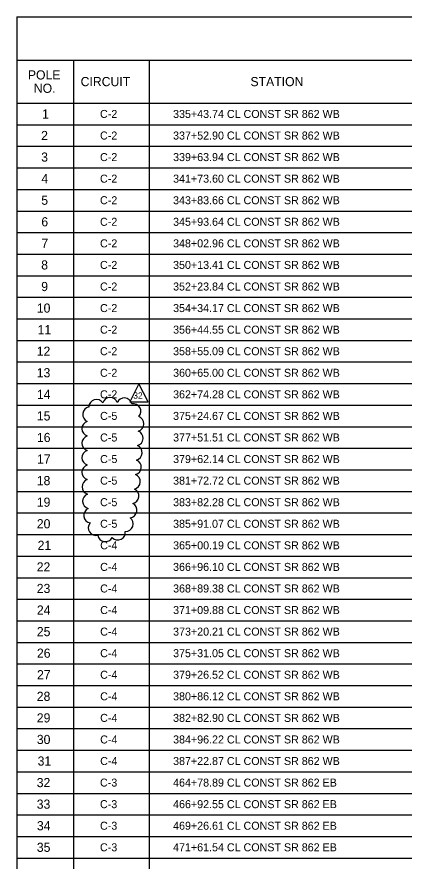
# Model space of a CAD drawing. Extents: x -818.1 to -802.4, y -2198.1 to -2187.9.
# Drawn here: x -817.24 to -814.27, y -2194.32 to -2187.86 of the extents above; entities that cross this region are included whole.
import ezdxf

# ---------------------------------------------------------------- set-up
doc = ezdxf.new("R2010")
doc.units = 0
for name, color, linetype in [('Cloud_dp', 7, 'Continuous'), ('SumBoxBorder_dp', 7, 'Continuous'), ('SumBoxLines_dp', 7, 'Continuous'), ('SumBoxLinesMin_dp', 7, 'Continuous'), ('TextLabel', 7, 'Continuous'), ('TextNotes', 7, 'Continuous')]:
    doc.layers.add(name, color=color, linetype=linetype)

msp = doc.modelspace()

# ---------------------------------------------------------------- linework, layer by layer
at = {"layer": 'Cloud_dp'}
for centre, radius, start, end in [((-816.6297, -2190.8434), 0.0582, 34.08748, 179.08748), ((-816.5257, -2190.8275), 0.0583, 18.3005, 163.3005), ((-816.4165, -2190.8314), 0.0583, 12.67782, 157.67782), ((-816.3478, -2190.8755), 0.0582, 316.71295, 101.71295), ((-816.6769, -2190.8997), 0.0583, 100.80604, 245.80604), ((-816.6833, -2191.0084), 0.0582, 107.5, 252.5), ((-816.3247, -2190.9704), 0.0582, 285.6373, 70.6373), ((-816.6833, -2191.1195), 0.0582, 107.5, 252.5), ((-816.3302, -2191.0807), 0.0582, 283.69742, 68.69742), ((-816.3376, -2191.1916), 0.0582, 283.69742, 68.69742), ((-816.6833, -2191.2306), 0.0582, 107.5, 252.5), ((-816.3449, -2191.3024), 0.0582, 283.69742, 68.69742), ((-816.6832, -2191.3417), 0.0582, 107.56018, 252.56018), ((-816.6822, -2191.4525), 0.0582, 108.55836, 253.55836), ((-816.3526, -2191.4132), 0.0582, 283.38206, 68.38206), ((-816.3626, -2191.5231), 0.0582, 281.1857, 66.1857), ((-816.6782, -2191.5629), 0.0582, 110.52167, 255.52167), ((-816.3785, -2191.6317), 0.0582, 277.15315, 62.15315), ((-816.6686, -2191.6722), 0.0582, 114.59135, 259.59135), ((-816.4065, -2191.7359), 0.0582, 267.75604, 52.75604), ((-816.6343, -2191.7667), 0.0582, 140.26847, 285.26847), ((-816.5613, -2191.8148), 0.0582, 187.97836, 332.97836), ((-816.4665, -2191.8018), 0.0582, 222.63242, 7.63242)]:
    msp.add_arc(centre, radius, start, end, dxfattribs=at)
at = {"layer": 'SumBoxBorder_dp'}
for p, q in [((-817.2394, -2187.8581), (-810.1144, -2187.8581)), ((-817.2394, -2187.8581), (-817.2394, -2195.9431)), ((-817.2394, -2188.1881), (-810.1144, -2188.1881)), ((-817.2394, -2188.1881), (-810.1144, -2188.1881))]:
    msp.add_line(p, q, dxfattribs=at)
at = {"layer": 'SumBoxLines_dp'}
for p, q in [((-816.8044, -2188.1881), (-816.8044, -2195.9431)), ((-816.8044, -2188.1881), (-816.8044, -2195.9431)), ((-816.2269, -2188.1881), (-816.2269, -2194.2931)), ((-816.2269, -2188.1881), (-816.2269, -2195.9431)), ((-817.2394, -2188.5181), (-810.1144, -2188.5181))]:
    msp.add_line(p, q, dxfattribs=at)
at = {"layer": 'SumBoxLinesMin_dp'}
for p, q in [((-817.2394, -2188.5181), (-810.1144, -2188.5181)), ((-817.2394, -2188.6831), (-810.1144, -2188.6831)), ((-817.2394, -2188.6831), (-810.1144, -2188.6831)), ((-817.2394, -2188.8481), (-810.1144, -2188.8481)), ((-817.2394, -2188.8481), (-810.1144, -2188.8481)), ((-817.2394, -2189.0131), (-810.1144, -2189.0131)), ((-817.2394, -2189.0131), (-810.1144, -2189.0131)), ((-817.2394, -2189.1781), (-810.1144, -2189.1781)), ((-817.2394, -2189.1781), (-810.1144, -2189.1781)), ((-817.2394, -2189.3431), (-810.1144, -2189.3431)), ((-817.2394, -2189.3431), (-810.1144, -2189.3431)), ((-817.2394, -2189.5081), (-810.1144, -2189.5081)), ((-817.2394, -2189.5081), (-810.1144, -2189.5081)), ((-817.2394, -2189.6731), (-810.1144, -2189.6731)), ((-817.2394, -2189.6731), (-810.1144, -2189.6731)), ((-817.2394, -2189.8381), (-810.1144, -2189.8381)), ((-817.2394, -2189.8381), (-810.1144, -2189.8381)), ((-817.2394, -2190.0031), (-810.1144, -2190.0031)), ((-817.2394, -2190.0031), (-810.1144, -2190.0031)), ((-817.2394, -2190.1681), (-810.1144, -2190.1681)), ((-817.2394, -2190.1681), (-810.1144, -2190.1681)), ((-817.2394, -2190.3331), (-810.1144, -2190.3331)), ((-817.2394, -2190.3331), (-810.1144, -2190.3331)), ((-817.2394, -2190.4981), (-810.1144, -2190.4981)), ((-817.2394, -2190.4981), (-810.1144, -2190.4981)), ((-817.2394, -2190.6631), (-810.1144, -2190.6631)), ((-817.2394, -2190.6631), (-810.1144, -2190.6631)), ((-817.2394, -2190.8281), (-810.1144, -2190.8281)), ((-817.2394, -2190.8281), (-810.1144, -2190.8281)), ((-817.2394, -2190.9931), (-810.1144, -2190.9931)), ((-817.2394, -2190.9931), (-810.1144, -2190.9931)), ((-817.2394, -2191.1581), (-810.1144, -2191.1581)), ((-817.2394, -2191.1581), (-810.1144, -2191.1581)), ((-817.2394, -2191.3231), (-810.1144, -2191.3231)), ((-817.2394, -2191.3231), (-810.1144, -2191.3231)), ((-817.2394, -2191.4881), (-810.1144, -2191.4881)), ((-817.2394, -2191.4881), (-810.1144, -2191.4881)), ((-817.2394, -2191.6531), (-810.1144, -2191.6531)), ((-817.2394, -2191.6531), (-810.1144, -2191.6531)), ((-817.2394, -2191.8181), (-810.1144, -2191.8181)), ((-817.2394, -2191.8181), (-810.1144, -2191.8181)), ((-817.2394, -2191.9831), (-810.1144, -2191.9831)), ((-817.2394, -2191.9831), (-810.1144, -2191.9831)), ((-817.2394, -2192.1481), (-810.1144, -2192.1481)), ((-817.2394, -2192.1481), (-810.1144, -2192.1481)), ((-817.2394, -2192.3131), (-810.1144, -2192.3131)), ((-817.2394, -2192.3131), (-810.1144, -2192.3131)), ((-817.2394, -2192.4781), (-810.1144, -2192.4781)), ((-817.2394, -2192.4781), (-810.1144, -2192.4781)), ((-817.2394, -2192.6431), (-810.1144, -2192.6431)), ((-817.2394, -2192.6431), (-810.1144, -2192.6431)), ((-817.2394, -2192.8081), (-810.1144, -2192.8081)), ((-817.2394, -2192.8081), (-810.1144, -2192.8081)), ((-817.2394, -2192.9731), (-810.1144, -2192.9731)), ((-817.2394, -2192.9731), (-810.1144, -2192.9731)), ((-817.2394, -2193.1381), (-810.1144, -2193.1381)), ((-817.2394, -2193.1381), (-810.1144, -2193.1381)), ((-817.2394, -2193.3031), (-810.1144, -2193.3031)), ((-817.2394, -2193.3031), (-810.1144, -2193.3031)), ((-817.2394, -2193.4681), (-810.1144, -2193.4681)), ((-817.2394, -2193.4681), (-810.1144, -2193.4681)), ((-817.2394, -2193.6331), (-810.1144, -2193.6331)), ((-817.2394, -2193.6331), (-810.1144, -2193.6331)), ((-817.2394, -2193.7981), (-810.1144, -2193.7981)), ((-817.2394, -2193.7981), (-810.1144, -2193.7981)), ((-817.2394, -2193.9631), (-810.1144, -2193.9631)), ((-817.2394, -2193.9631), (-810.1144, -2193.9631)), ((-817.2394, -2194.1281), (-816.2269, -2194.1281)), ((-817.2394, -2194.1281), (-810.1144, -2194.1281)), ((-817.2394, -2194.2931), (-810.1144, -2194.2931)), ((-817.2394, -2194.2931), (-810.1144, -2194.2931))]:
    msp.add_line(p, q, dxfattribs=at)
at = {"layer": 'TextNotes'}
msp.add_lwpolyline([(-816.3042, -2190.6665), (-816.3753, -2190.8033), (-816.2332, -2190.8033)], close=True, dxfattribs=at)

# ---------------------------------------------------------------- texts
at = {"layer": 'TextLabel'}
for s, height, p in [('POLE', 0.07, (-817.1552, -2188.3371)), ('NO.', 0.07, (-817.1096, -2188.4391)), ('CIRCUIT', 0.07, (-816.751, -2188.3881)), ('STATION', 0.07, (-815.4503, -2188.3881)), ('1', 0.07, (-817.0466, -2188.6356)), ('C-2', 0.06125, (-816.6024, -2188.6313)), ('335+43.74 CL CONST SR 862 WB', 0.06125, (-816.0428, -2188.6313)), ('2', 0.07, (-817.0533, -2188.8006)), ('C-2', 0.06125, (-816.6024, -2188.7963)), ('337+52.90 CL CONST SR 862 WB', 0.06125, (-816.0428, -2188.7963)), ('3', 0.07, (-817.0533, -2188.9656)), ('C-2', 0.06125, (-816.6024, -2188.9613)), ('339+63.94 CL CONST SR 862 WB', 0.06125, (-816.0428, -2188.9613)), ('4', 0.07, (-817.0519, -2189.1306)), ('C-2', 0.06125, (-816.6024, -2189.1263)), ('341+73.60 CL CONST SR 862 WB', 0.06125, (-816.0428, -2189.1263)), ('5', 0.07, (-817.0524, -2189.2956)), ('C-2', 0.06125, (-816.6024, -2189.2913)), ('343+83.66 CL CONST SR 862 WB', 0.06125, (-816.0428, -2189.2913)), ('6', 0.07, (-817.0519, -2189.4606)), ('C-2', 0.06125, (-816.6024, -2189.4563)), ('345+93.64 CL CONST SR 862 WB', 0.06125, (-816.0428, -2189.4563)), ('7', 0.07, (-817.0513, -2189.6256)), ('C-2', 0.06125, (-816.6024, -2189.6213)), ('348+02.96 CL CONST SR 862 WB', 0.06125, (-816.0428, -2189.6213)), ('8', 0.07, (-817.0531, -2189.7906)), ('C-2', 0.06125, (-816.6024, -2189.7863)), ('350+13.41 CL CONST SR 862 WB', 0.06125, (-816.0428, -2189.7863)), ('9', 0.07, (-817.0529, -2189.9556)), ('C-2', 0.06125, (-816.6024, -2189.9513)), ('352+23.84 CL CONST SR 862 WB', 0.06125, (-816.0428, -2189.9513)), ('10', 0.07, (-817.0866, -2190.1206)), ('C-2', 0.06125, (-816.6024, -2190.1163)), ('354+34.17 CL CONST SR 862 WB', 0.06125, (-816.0428, -2190.1163)), ('11', 0.07, (-817.0805, -2190.2856)), ('C-2', 0.06125, (-816.6024, -2190.2813)), ('356+44.55 CL CONST SR 862 WB', 0.06125, (-816.0428, -2190.2813)), ('12', 0.07, (-817.0872, -2190.4506)), ('C-2', 0.06125, (-816.6024, -2190.4463)), ('358+55.09 CL CONST SR 862 WB', 0.06125, (-816.0428, -2190.4463)), ('13', 0.07, (-817.0872, -2190.6156)), ('C-2', 0.06125, (-816.6024, -2190.6113)), ('360+65.00 CL CONST SR 862 WB', 0.06125, (-816.0428, -2190.6113)), ('14', 0.07, (-817.0858, -2190.7806)), ('C-2', 0.06125, (-816.6024, -2190.7763)), ('362+74.28 CL CONST SR 862 WB', 0.06125, (-816.0428, -2190.7763)), ('15', 0.07, (-817.0863, -2190.9456)), ('C-5', 0.06125, (-816.6017, -2190.9413)), ('375+24.67 CL CONST SR 862 WB', 0.06125, (-816.0428, -2190.9413)), ('16', 0.07, (-817.0858, -2191.1106)), ('C-5', 0.06125, (-816.6017, -2191.1063)), ('377+51.51 CL CONST SR 862 WB', 0.06125, (-816.0428, -2191.1063)), ('17', 0.07, (-817.0852, -2191.2756)), ('C-5', 0.06125, (-816.6017, -2191.2713)), ('379+62.14 CL CONST SR 862 WB', 0.06125, (-816.0428, -2191.2713)), ('18', 0.07, (-817.0869, -2191.4406)), ('C-5', 0.06125, (-816.6017, -2191.4363)), ('381+72.72 CL CONST SR 862 WB', 0.06125, (-816.0428, -2191.4363)), ('19', 0.07, (-817.0868, -2191.6056)), ('C-5', 0.06125, (-816.6017, -2191.6013)), ('383+82.28 CL CONST SR 862 WB', 0.06125, (-816.0428, -2191.6013)), ('20', 0.07, (-817.0866, -2191.7706)), ('C-5', 0.06125, (-816.6017, -2191.7663)), ('385+91.07 CL CONST SR 862 WB', 0.06125, (-816.0428, -2191.7663)), ('21', 0.07, (-817.0805, -2191.9356)), ('C-4', 0.06125, (-816.6012, -2191.9313)), ('365+00.19 CL CONST SR 862 WB', 0.06125, (-816.0428, -2191.9313)), ('22', 0.07, (-817.0872, -2192.1006)), ('C-4', 0.06125, (-816.6012, -2192.0963)), ('366+96.10 CL CONST SR 862 WB', 0.06125, (-816.0428, -2192.0963)), ('23', 0.07, (-817.0872, -2192.2656)), ('C-4', 0.06125, (-816.6012, -2192.2613)), ('368+89.38 CL CONST SR 862 WB', 0.06125, (-816.0428, -2192.2613)), ('24', 0.07, (-817.0858, -2192.4306)), ('C-4', 0.06125, (-816.6012, -2192.4263)), ('371+09.88 CL CONST SR 862 WB', 0.06125, (-816.0428, -2192.4263)), ('25', 0.07, (-817.0863, -2192.5956)), ('C-4', 0.06125, (-816.6012, -2192.5913)), ('373+20.21 CL CONST SR 862 WB', 0.06125, (-816.0428, -2192.5913)), ('26', 0.07, (-817.0858, -2192.7606)), ('C-4', 0.06125, (-816.6012, -2192.7563)), ('375+31.05 CL CONST SR 862 WB', 0.06125, (-816.0428, -2192.7563)), ('27', 0.07, (-817.0852, -2192.9256)), ('C-4', 0.06125, (-816.6012, -2192.9213)), ('379+26.52 CL CONST SR 862 WB', 0.06125, (-816.0428, -2192.9213)), ('28', 0.07, (-817.0869, -2193.0906)), ('C-4', 0.06125, (-816.6012, -2193.0863)), ('380+86.12 CL CONST SR 862 WB', 0.06125, (-816.0428, -2193.0863)), ('29', 0.07, (-817.0868, -2193.2556)), ('C-4', 0.06125, (-816.6012, -2193.2513)), ('382+82.90 CL CONST SR 862 WB', 0.06125, (-816.0428, -2193.2513)), ('30', 0.07, (-817.0866, -2193.4206)), ('C-4', 0.06125, (-816.6012, -2193.4163)), ('384+96.22 CL CONST SR 862 WB', 0.06125, (-816.0428, -2193.4163)), ('31', 0.07, (-817.0805, -2193.5856)), ('C-4', 0.06125, (-816.6012, -2193.5813)), ('387+22.87 CL CONST SR 862 WB', 0.06125, (-816.0428, -2193.5813)), ('32', 0.07, (-817.0872, -2193.7506)), ('C-3', 0.06125, (-816.6025, -2193.7463)), ('464+78.89 CL CONST SR 862 EB', 0.06125, (-816.0428, -2193.7463)), ('33', 0.07, (-817.0872, -2193.9156)), ('C-3', 0.06125, (-816.6025, -2193.9113)), ('466+92.55 CL CONST SR 862 EB', 0.06125, (-816.0428, -2193.9113)), ('34', 0.07, (-817.0858, -2194.0806)), ('C-3', 0.06125, (-816.6025, -2194.0763)), ('469+26.61 CL CONST SR 862 EB', 0.06125, (-816.0428, -2194.0763)), ('35', 0.07, (-817.0863, -2194.2456)), ('C-3', 0.06125, (-816.6025, -2194.2413)), ('471+61.54 CL CONST SR 862 EB', 0.06125, (-816.0428, -2194.2413))]:
    msp.add_text(s, height=height, dxfattribs=at).set_placement(p)
at = {"layer": 'TextNotes'}
msp.add_text('32', height=0.04842, rotation=360, dxfattribs=at).set_placement((-816.348, -2190.779))

doc.saveas('drawing.dxf')
